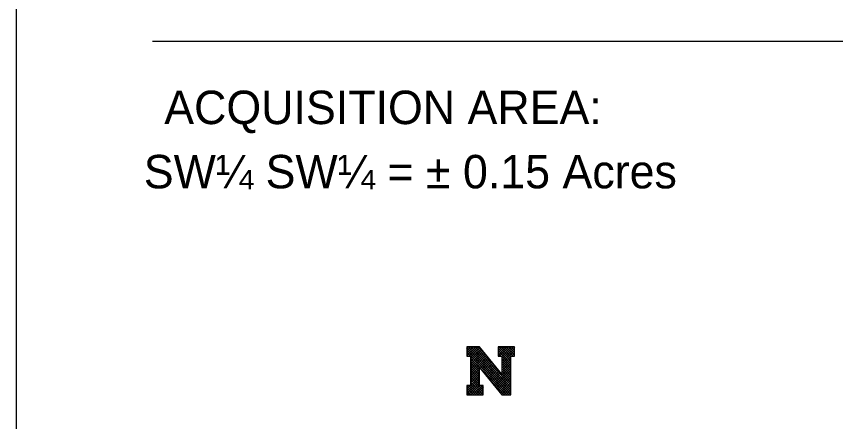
# Model space of a CAD drawing. Extents: x 23379288 to 23380138, y 6801100 to 6802500.
# Drawn here: x 23379287.8 to 23379532.6, y 6802132.6 to 6802253.7 of the extents above; entities that cross this region are included whole.
import ezdxf

# ---------------------------------------------------------------- set-up
doc = ezdxf.new("R2010")
doc.units = 0
for name, color, linetype in [('DisPlatCells', 7, 'Continuous'), ('DisPlatData', 7, 'Continuous'), ('Level 60', 7, 'Continuous')]:
    doc.layers.add(name, color=color, linetype=linetype)

msp = doc.modelspace()

# ---------------------------------------------------------------- linework, layer by layer
at = {"layer": 'DisPlatCells'}
for p, q in [((23379328.47, 6802246.26), (23380063.5, 6802246.26)), ((23379426.22, 6802154.89), (23379422.37, 6802154.89)), ((23379422.37, 6802154.89), (23379422.37, 6802152.14)), ((23379422.37, 6802152.21), (23379425.04, 6802154.89)), ((23379422.37, 6802152.92), (23379424.33, 6802154.89)), ((23379422.37, 6802153.63), (23379423.63, 6802154.89)), ((23379422.37, 6802154.34), (23379422.92, 6802154.89)), ((23379422.37, 6802154.69), (23379435.57, 6802141.49)), ((23379422.88, 6802154.89), (23379435.57, 6802142.2)), ((23379423, 6802152.14), (23379425.75, 6802154.89)), ((23379423.47, 6802151.9), (23379426.32, 6802154.76)), ((23379423.59, 6802154.89), (23379435.57, 6802142.91)), ((23379424.29, 6802154.89), (23379435.57, 6802143.62)), ((23379425, 6802154.89), (23379431.38, 6802148.5)), ((23379425.71, 6802154.89), (23379428.38, 6802152.22)), ((23379432.82, 6802146.74), (23379426.22, 6802154.89)), ((23379436.67, 6802154.89), (23379431.72, 6802154.89)), ((23379431.72, 6802154.89), (23379431.72, 6802152.14)), ((23379431.72, 6802152.37), (23379434.23, 6802154.89)), ((23379431.72, 6802153.08), (23379433.53, 6802154.89)), ((23379431.72, 6802153.79), (23379432.82, 6802154.89)), ((23379431.72, 6802154.49), (23379432.11, 6802154.89)), ((23379432.07, 6802154.89), (23379435.57, 6802151.39)), ((23379432.19, 6802152.14), (23379434.94, 6802154.89)), ((23379432.78, 6802154.89), (23379435.57, 6802152.1)), ((23379432.82, 6802151.35), (23379436.36, 6802154.89)), ((23379432.82, 6802152.06), (23379435.65, 6802154.89)), ((23379433.49, 6802154.89), (23379436.24, 6802152.14)), ((23379434.19, 6802154.89), (23379436.67, 6802152.41)), ((23379434.9, 6802154.89), (23379436.67, 6802153.12)), ((23379435.61, 6802154.89), (23379436.67, 6802153.83)), ((23379436.32, 6802154.89), (23379436.67, 6802154.54)), ((23379436.67, 6802152.14), (23379436.67, 6802154.89)), ((23379422.37, 6802153.99), (23379435.57, 6802140.79)), ((23379422.37, 6802153.28), (23379435.06, 6802140.59)), ((23379422.37, 6802152.57), (23379422.8, 6802152.14)), ((23379423.47, 6802151.19), (23379426.64, 6802154.37)), ((23379423.47, 6802150.49), (23379426.96, 6802153.98)), ((23379423.47, 6802149.78), (23379427.27, 6802153.58)), ((23379423.47, 6802149.07), (23379427.59, 6802153.19)), ((23379423.47, 6802148.36), (23379427.9, 6802152.8)), ((23379423.47, 6802147.66), (23379428.22, 6802152.41)), ((23379431.72, 6802154.54), (23379435.57, 6802150.69)), ((23379431.72, 6802153.83), (23379435.57, 6802149.98)), ((23379431.72, 6802153.12), (23379432.7, 6802152.14)), ((23379431.72, 6802152.41), (23379431.99, 6802152.14)), ((23379432.82, 6802150.64), (23379436.67, 6802154.49)), ((23379432.82, 6802149.94), (23379436.67, 6802153.79)), ((23379435.73, 6802152.14), (23379436.67, 6802153.08)), ((23379436.43, 6802152.14), (23379436.67, 6802152.37)), ((23379422.37, 6802152.14), (23379423.47, 6802152.14)), ((23379423.47, 6802152.14), (23379423.47, 6802143.34)), ((23379423.47, 6802146.95), (23379428.54, 6802152.02)), ((23379423.47, 6802146.24), (23379428.85, 6802151.63)), ((23379423.47, 6802151.47), (23379426.22, 6802148.72)), ((23379423.47, 6802150.77), (23379426.22, 6802148.02)), ((23379423.47, 6802150.06), (23379426.22, 6802147.31)), ((23379426.42, 6802148.49), (23379429.17, 6802151.24)), ((23379426.74, 6802148.1), (23379429.49, 6802150.85)), ((23379427.05, 6802147.71), (23379429.8, 6802150.46)), ((23379427.37, 6802147.32), (23379430.12, 6802150.07)), ((23379431.72, 6802152.14), (23379432.82, 6802152.14)), ((23379432.82, 6802152.14), (23379432.82, 6802146.74)), ((23379432.82, 6802152.02), (23379435.57, 6802149.27)), ((23379432.82, 6802149.23), (23379435.57, 6802151.98)), ((23379432.82, 6802151.31), (23379435.57, 6802148.56)), ((23379432.82, 6802148.52), (23379435.57, 6802151.27)), ((23379432.82, 6802150.61), (23379435.57, 6802147.86)), ((23379432.82, 6802147.82), (23379435.57, 6802150.57)), ((23379432.82, 6802149.9), (23379435.57, 6802147.15)), ((23379432.82, 6802147.11), (23379435.57, 6802149.86)), ((23379435.57, 6802140.59), (23379435.57, 6802152.14)), ((23379435.57, 6802152.14), (23379436.67, 6802152.14)), ((23379423.47, 6802149.35), (23379426.22, 6802146.6)), ((23379423.47, 6802148.64), (23379426.22, 6802145.89)), ((23379423.47, 6802145.54), (23379426.22, 6802148.29)), ((23379423.47, 6802147.94), (23379426.22, 6802145.19)), ((23379423.47, 6802144.83), (23379426.22, 6802147.58)), ((23379426.22, 6802143.34), (23379426.22, 6802148.74)), ((23379426.22, 6802148.74), (23379432.82, 6802140.59)), ((23379426.3, 6802148.64), (23379434.35, 6802140.59)), ((23379427.69, 6802146.93), (23379430.44, 6802149.68)), ((23379428, 6802146.54), (23379430.75, 6802149.29)), ((23379428.32, 6802146.15), (23379431.07, 6802148.9)), ((23379428.63, 6802145.75), (23379431.38, 6802148.5)), ((23379428.95, 6802145.36), (23379431.7, 6802148.11)), ((23379429.27, 6802144.97), (23379432.02, 6802147.72)), ((23379429.58, 6802144.58), (23379432.33, 6802147.33)), ((23379430.22, 6802143.8), (23379435.57, 6802149.15)), ((23379430.53, 6802143.41), (23379435.57, 6802148.44)), ((23379430.85, 6802143.02), (23379435.57, 6802147.74)), ((23379432.82, 6802149.19), (23379435.57, 6802146.44)), ((23379432.82, 6802148.49), (23379435.57, 6802145.74)), ((23379432.82, 6802147.78), (23379435.57, 6802145.03)), ((23379422.37, 6802141.61), (23379426.22, 6802145.46)), ((23379423.47, 6802147.23), (23379426.22, 6802144.48)), ((23379423.47, 6802144.12), (23379426.22, 6802146.87)), ((23379423.47, 6802146.52), (23379426.22, 6802143.77)), ((23379423.47, 6802143.41), (23379426.22, 6802146.16)), ((23379423.47, 6802145.82), (23379427.32, 6802141.97)), ((23379423.47, 6802145.11), (23379427.32, 6802141.26)), ((23379429.3, 6802144.93), (23379433.64, 6802140.59)), ((23379429.9, 6802144.19), (23379432.65, 6802146.94)), ((23379431.17, 6802142.63), (23379435.57, 6802147.03)), ((23379431.48, 6802142.24), (23379435.57, 6802146.32)), ((23379431.8, 6802141.85), (23379435.57, 6802145.62)), ((23379432.11, 6802141.46), (23379435.57, 6802144.91)), ((23379432.82, 6802147.07), (23379435.57, 6802144.32)), ((23379422.37, 6802140.9), (23379426.22, 6802144.75)), ((23379423.47, 6802143.34), (23379422.37, 6802143.34)), ((23379422.37, 6802143.34), (23379422.37, 6802140.59)), ((23379422.37, 6802142.31), (23379423.39, 6802143.34)), ((23379422.37, 6802143.02), (23379422.68, 6802143.34)), ((23379422.37, 6802142.67), (23379424.45, 6802140.59)), ((23379422.41, 6802143.34), (23379425.16, 6802140.59)), ((23379422.76, 6802140.59), (23379426.22, 6802144.04)), ((23379423.12, 6802143.34), (23379425.87, 6802140.59)), ((23379423.47, 6802144.4), (23379427.28, 6802140.59)), ((23379423.47, 6802143.69), (23379426.57, 6802140.59)), ((23379423.47, 6802140.59), (23379426.22, 6802143.34)), ((23379424.18, 6802140.59), (23379426.93, 6802143.34)), ((23379424.88, 6802140.59), (23379427.32, 6802143.02)), ((23379427.32, 6802143.34), (23379426.22, 6802143.34)), ((23379426.65, 6802143.34), (23379427.32, 6802142.67)), ((23379427.32, 6802140.59), (23379427.32, 6802143.34)), ((23379432.43, 6802141.07), (23379435.57, 6802144.2)), ((23379432.75, 6802140.67), (23379435.57, 6802143.49)), ((23379433.37, 6802140.59), (23379435.57, 6802142.79)), ((23379422.37, 6802141.97), (23379423.74, 6802140.59)), ((23379422.37, 6802141.26), (23379423.04, 6802140.59)), ((23379422.37, 6802140.59), (23379427.32, 6802140.59)), ((23379425.59, 6802140.59), (23379427.32, 6802142.32)), ((23379426.3, 6802140.59), (23379427.32, 6802141.61)), ((23379427, 6802140.59), (23379427.32, 6802140.9)), ((23379432.31, 6802141.22), (23379432.94, 6802140.59)), ((23379432.82, 6802140.59), (23379435.57, 6802140.59)), ((23379434.08, 6802140.59), (23379435.57, 6802142.08)), ((23379434.78, 6802140.59), (23379435.57, 6802141.37)), ((23379435.49, 6802140.59), (23379435.57, 6802140.67))]:
    msp.add_line(p, q, dxfattribs=at)
at = {"layer": 'Level 60'}
msp.add_line((23379287.77, 6801100.45), (23379287.77, 6802500.47), dxfattribs=at)

# ---------------------------------------------------------------- texts
at = {"layer": 'DisPlatData'}
for s, p in [('ACQUISITION AREA:', (23379331.96, 6802221.49)), ('   SW¼ SW¼ = %%P 0.15 Acres', (23379314.7, 6802202.29))]:
    msp.add_text(s, height=10.0002, dxfattribs=at).set_placement(p)

doc.saveas('drawing.dxf')
